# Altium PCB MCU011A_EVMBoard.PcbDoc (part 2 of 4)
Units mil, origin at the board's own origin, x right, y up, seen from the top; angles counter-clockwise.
Board outline 10115 x 9285 mil, 4 copper layers (Top Layer, GND, PWR, Bottom Layer), stack 61.2 mil thick; 438 components, 207 nets, 1196 pads, 248 vias.
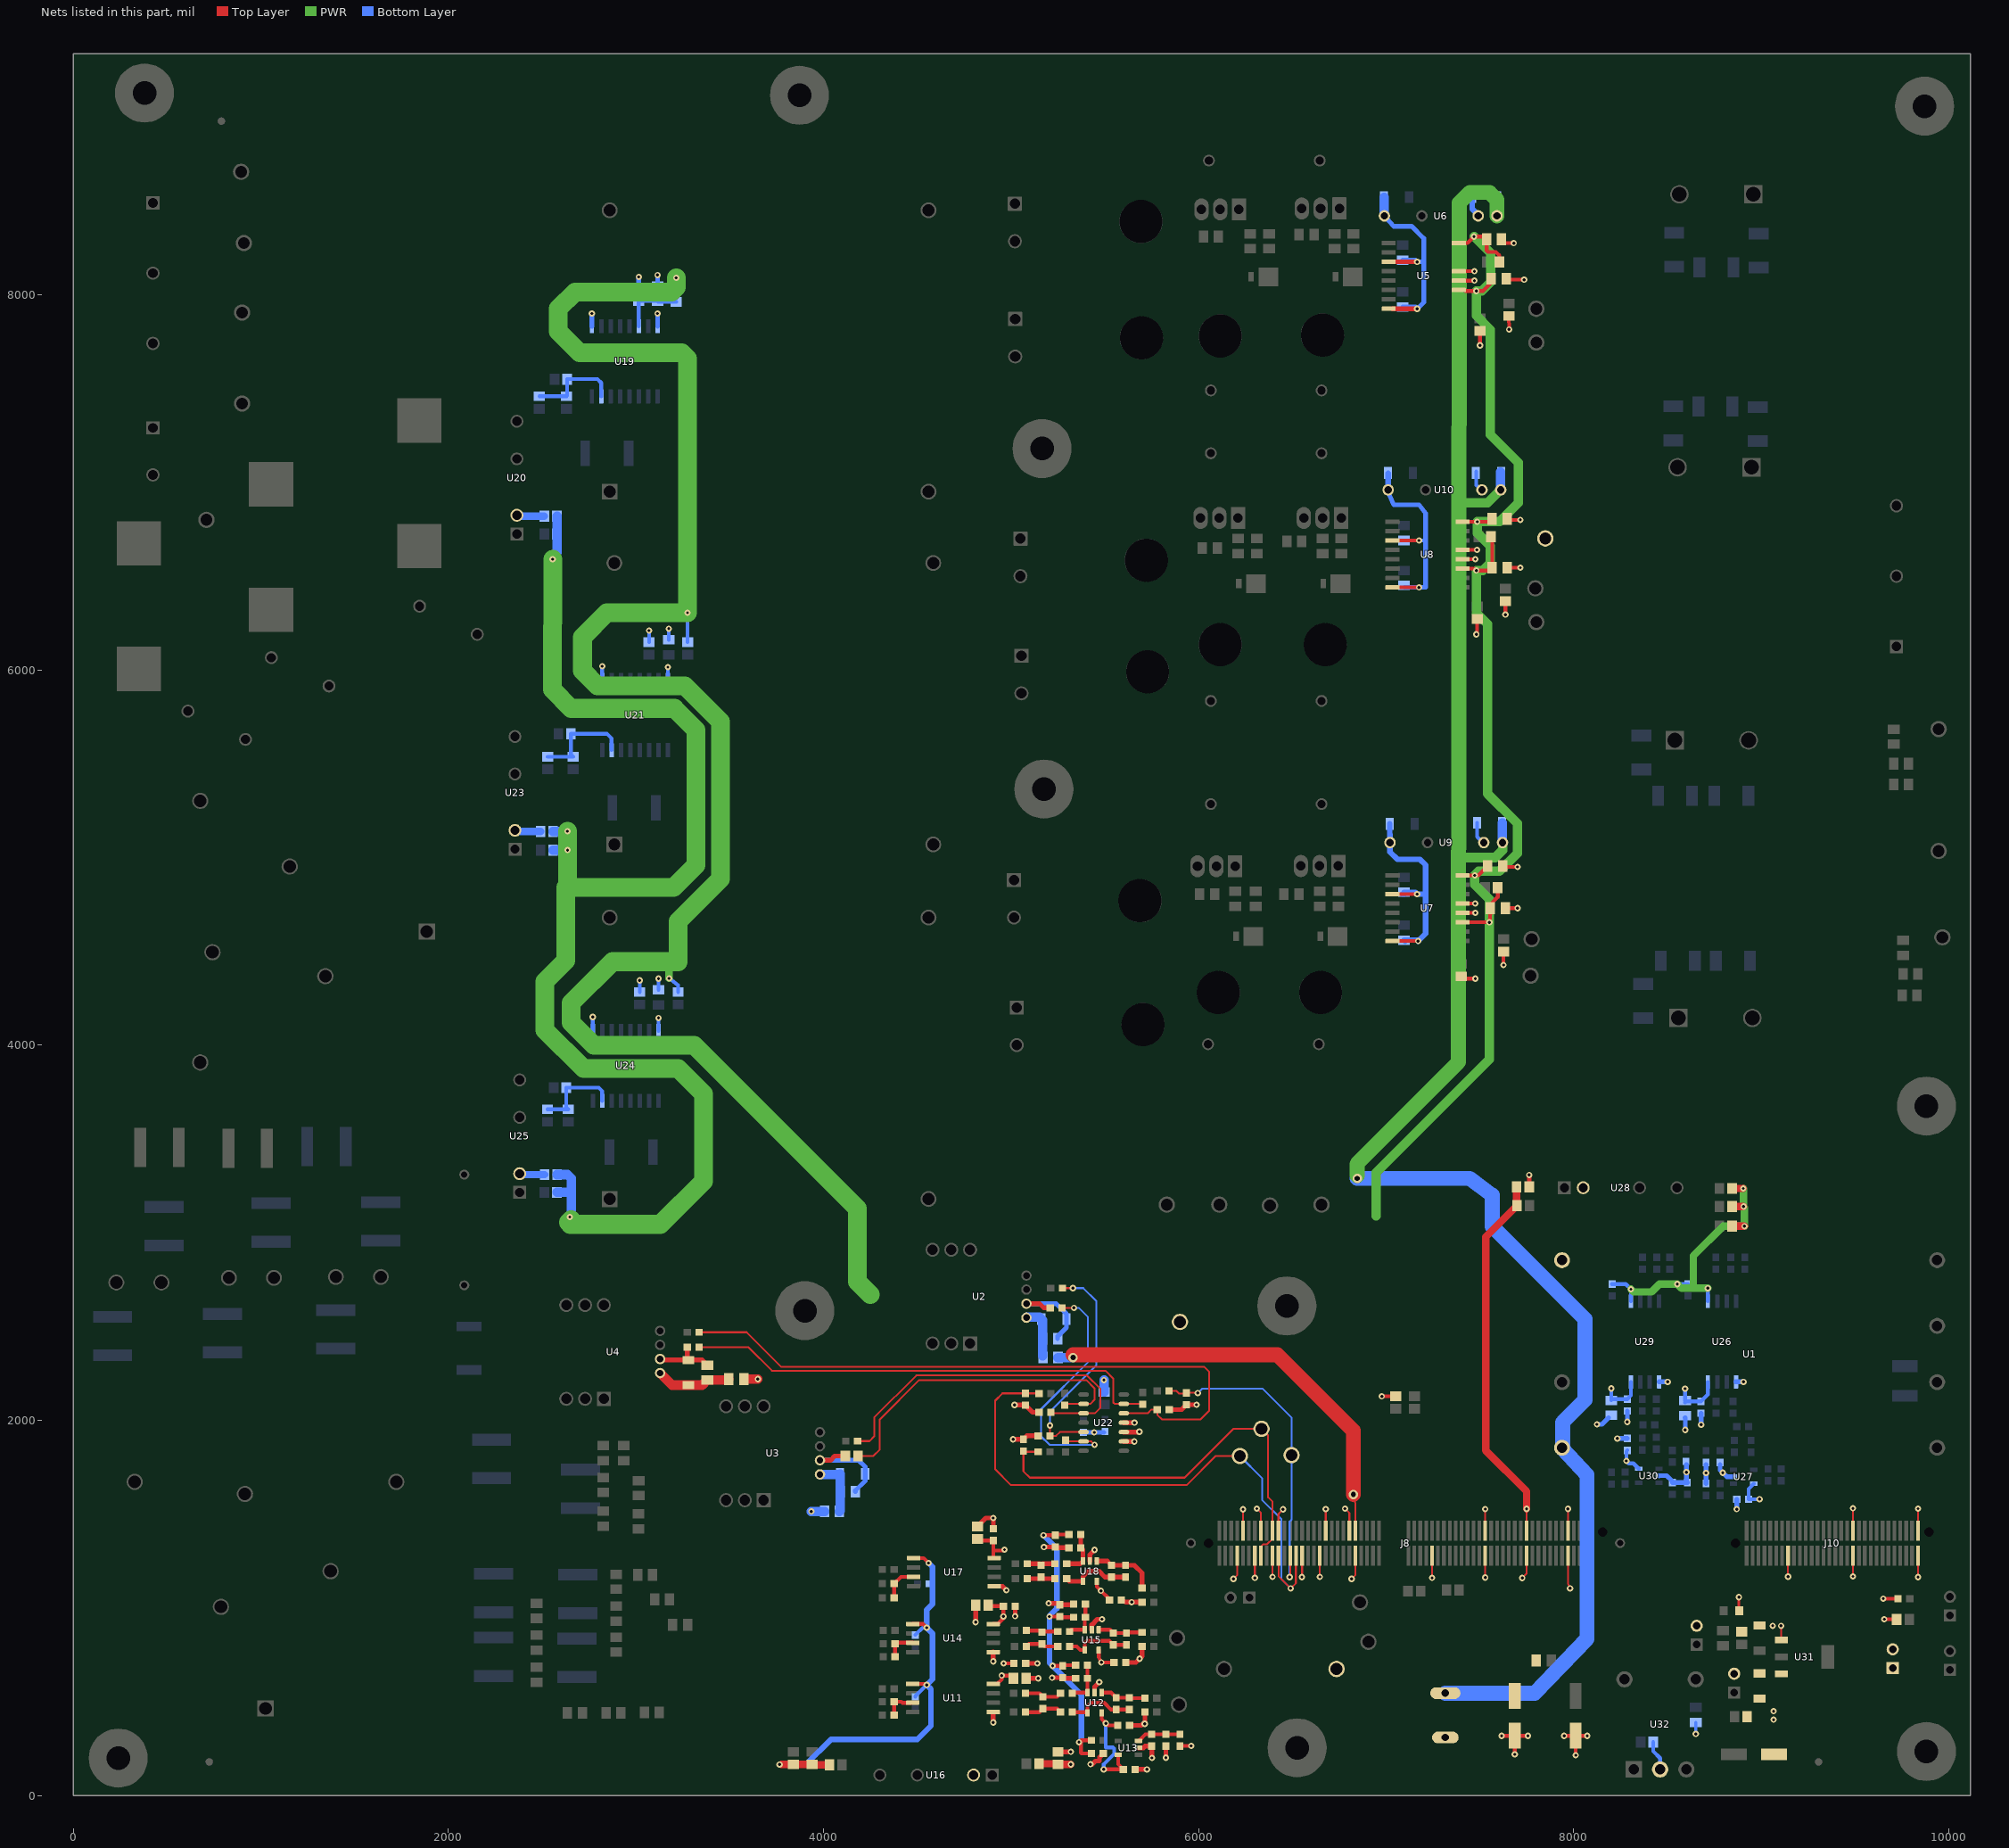
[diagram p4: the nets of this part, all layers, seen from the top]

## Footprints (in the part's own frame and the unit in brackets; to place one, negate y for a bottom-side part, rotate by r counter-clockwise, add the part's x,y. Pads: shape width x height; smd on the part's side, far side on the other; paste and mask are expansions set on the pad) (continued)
Phoenix_1714984 [mm] "Phoenix Contact"
  rect 1.8x1.8 hole 1.3 paste+0: 1(-9.52,1.65)
  round 1.8 hole 1.3 paste+0: 2(0,1.65) 3(9.52,1.65)
  silkscreen extent -14.85,-6.81 14.28,6.25, body extent -14.85,-6.25 14.28,6.25, height 21.51
POWERMITE [mil] "On Semi recommended land pattern, 457-04.pdf Rev 04E dated 2008-11-26"
  rect 105x100 smd: 1(-46,0)
  rect 30x50 smd: 2(46,0)
  silkscreen extent -124,-63 61,63, body extent -94,-40 59,40, height 45
PWR050 [mil] "TI PCBA"
  round 85 hole 55: 1(-1000,500) 2(-1000,-500) 3(-1000,150) 4(-1000,-150) 5(1000,500) 6(1000,150) 7(1000,-500)
  silkscreen extent -1100,-600 1100,600, body extent -1100,-600 1100,600, height 356
RP-1205S [mm] "Recom Power"
  round 1.55 hole 1: 1(-7.62,2.54) 2(-5.08,2.54) 5(2.54,2.54) 7(7.62,2.54)
  silkscreen extent -9.62,-3.24 10.03,3.81, body extent -9.62,-3.24 10.03,3.81, height 10.21
Samtec_HTSW-102-07-G-S [mm] "Samtec 100mil, 1x2, 230 mil above insulator"
  rrect6% 1.65x1.65 hole 1.016: 1(-1.27,0)
  round 1.65 hole 1.016: 2(1.27,0)
  silkscreen extent -3.3,-1.27 2.54,1.27, body extent -2.54,-1.27 2.54,1.27, height 8.38
SM_RADIAL_6.3BMM [mm] "Nichicon 6.3x7.7"
  rect 3.5x1.6 smd: 1(-2.7,0) 2(2.7,0)
  silkscreen extent -3.4,-3.4 3.4,3.4, body extent -3.4,-3.4 3.4,3.4, height 8
TI_Stacked_Overlay_Small [mil]
  silkscreen extent -418,-98 418,98
TO-220-2_HORIZ_INV [mm] "TO-220, 2-Leads, Horizontal"
  rrect5% 1.9x1.9 hole 1.4: 1(-2.54,0)
  round 1.9 hole 1.4: 2(2.54,0)
  silkscreen extent -5,-20.25 5,-1.3, body extent -5,-20.25 5,0.35, height 4.5
TO-220AB_HORIZONTAL [mil] "For SolarMagic, with tab facing heatsink, away from PCB"
  rrect5% 76x118.11 hole 50: 1(100,0)
  rrect100% 76x118.11 hole 50: 2(0,0) 3(-100,0)
  silkscreen extent -210,79 210,800, body extent -210,-12 210,800, height 192
WL-SMCW_Green_0805 [mm] "SMD, 2-Leads, Body 2x1.25mm"
  rect 1.1x1.2 smd: 1(-1.05,0) 2(1.05,0)
  silkscreen extent -2.4,-1.1 1.5,1.1, body extent -1,-0.62 1,0.63, height 0.7

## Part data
C1: "CAP, CERM, 0.47 µF, 500 V, +/- 10%, X7R, 1812", Cap_Case=1812, Manufacturer="Knowles Capacitors", Supplier Part Number 1=1608-1155-1-ND, TempCo=X7R, Tolerance_%=10, Value1=Unknown, Value2=500V, ValueDisplayed=0.47µF
C2 C4 C6 C12 C13 C21 C22 C24 C25 C109 C111: "CAP, CERM, 10 µF, 25 V, +/- 10%, X7R, 1206_190", Cap_Case=1206, Manufacturer=Kemet, Supplier Part Number 1=399-7442-1-ND, TempCo=X7R, Tolerance_%=10, Value1=Unknown, Value2=25V, ValueDisplayed=10µF
C3 C5 C7 C8 C9 C11 C14 C15 C17 C18 C20 C23 C55 C63 C66 C67 C73 C77 C81 C93 C103 C105 C108 C110: "CAP, CERM, 0.1 µF, 25 V, +/- 10%, X7R, 0805", Cap_Case=0805, Manufacturer=Kemet, Supplier Part Number 1=399-1168-1-ND, TempCo=X7R, Tolerance_%=10, Value1="0.064 ohm", Value2=25V, ValueDisplayed=0.1µF
C10 C16 C19 C53 C54 C64 C65 C71 C72 C79 C80 C91 C92: "CAP, CERM, 1 µF, 50 V, +/- 10%, X7R, 0805", Cap_Case=0805, Manufacturer=MuRata, Supplier Part Number 1=490-4736-1-ND, TempCo=X7R, Tolerance_%=10, Value1=Unknown, Value2=50V, ValueDisplayed=1µF
C26 C31 C34 C35 C39 C44 C46 C47 C49 C57 C59 C60 C82 C87 C89 C90 C94 C99 C101 C102: "CAP, CERM, 180 pF, 50 V, +/- 5%, C0G/NP0, 0603", Cap_Case=0603, Manufacturer=Kemet, Supplier Part Number 1=399-1064-1-ND, TempCo=C0G/NP0, Tolerance_%=5, Value1=Unknown, Value2=50V, ValueDisplayed=180pF
C27 C29 C30 C32 C33 C36 C37 C38 C40 C42 C43 C45 C48 C50 C52 C56 C58 C61 C69 C74 C75 C78 C83 C85 C86 C88 C95 C97 C98 C100: "CAP, CERM, 0.1 µF, 16 V, +/- 5%, X7R, 0603", Cap_Case=0603, Manufacturer=AVX, Supplier Part Number 1=478-3726-1-ND, TempCo=X7R, Tolerance_%=5, Value1="0.039 ohm", Value2=16V, ValueDisplayed=0.1µF
C28 C41 C51 C84 C96: "CAP, CERM, 4.7 µF, 50 V, +/- 10%, X5R, 0805", Cap_Case=0805, Manufacturer=TDK, Supplier Part Number 1=445-5980-1-ND, TempCo=X5R, Tolerance_%=10, Value1=Unknown, Value2=50V, ValueDisplayed=4.7µF
C62 C68 C76: "CAP, CERM, 2.2 µF, 16 V, +/- 10%, X5R, 0805", Cap_Case=0805, Manufacturer=AVX, Supplier Part Number 1=478-2580-1-ND, TempCo=X5R, Tolerance_%=10, Value1="0.009 ohm", Value2=16V, ValueDisplayed=2.2µF
C70: "CAP, CERM, 1 µF, 25 V, +/- 10%, X7R, 0603", Cap_Case=0603, Manufacturer=Kemet, Supplier Part Number 1=399-7376-1-ND, TempCo=X7R, Tolerance_%=10, Value1=Unknown, Value2=25V, ValueDisplayed=1µF
C104 C106 C107: library part EEHZA1E101XP, "CAP, Polymer Hybrid, 100 µF, 25 V, +/- 20%, 30 ohm, 6.3x7.7 SMD", Manufacturer=Panasonic, Supplier Part Number 1=P15436CT-ND, Tolerance_%=20, Value1="30 ohm", Value2=25V, ValueDisplayed=100µF
"CAUTION High Voltage" "CAUTION! High Voltage" "CAUTION! High Voltage Input" "CAUTION! High Voltage Output" "CAUTION! High Voltage!" "CAUTION! High Voltage!!" "CAUTION!! High Voltage" "CAUTION!! High Voltage!!!" "CAUTION!!! High Voltage!!!": library part IEC_HighVoltage, "IEC 61010-1 High Voltage Warning"
"CAUTION! HOT SURFACE!" "CAUTION! HOT SURFACE!!": library part IEC_HotSurface, "IEC 61010-1 Hot Surface Warning"
"CAUTION! Read User Guide Before Operating": library part IEC_Caution, "IEC 61010-1 Caution Warning"
Cbus1 Cbus4 Cbus5 Cbus6 Cbus7 Cbus10: "CAP, Film, 0.1 µF, 630 V, +/- 5%, TH", Cap_Case="Radial 18x7.7x13.6", Manufacturer=Panasonic, Supplier Part Number 1=P12158-ND, Tolerance_%=5, Value1=Unknown, Value2=630V, ValueDisplayed=0.1µF
Cbus2 Cbus3 Cbus8 Cbus9: "CAP, AL, 220 µF, 450 V, +/- 20%, 0.73 ohm, TH", Cap_Case=35x30mm, Manufacturer=TDK, Supplier Part Number 1=495-4262-ND, Tolerance_%=20, Value1="0.73 ohm", Value2=450V, ValueDisplayed=220µF
Cm1: "CAP, Film, 0.1 µF, 275 V, +/- 20%, TH", Cap_Case="Radial 17.5x5.5x12.5", Manufacturer=Panasonic, Supplier Part Number 1=P10730-ND, Tolerance_%=20, Value1=Unknown, Value2=275V, ValueDisplayed=0.1µF
Cvn1 Cvn2 Cvn3 Cvn4 Cvn5 Cvn6 Cx1 Cx2 Cx3 Cx4 Cx5 Cx6 Cy1 Cy2 Cy3: "CAP, CERM, 2200 pF, 250 V, +/- 10%, X7R, 2220", Cap_Case=2220, Manufacturer=MuRata, Supplier Part Number 1=490-3480-1-ND, TempCo=X7R, Tolerance_%=10, Value1=Unknown, Value2=250V, ValueDisplayed=2200pF
D1 D2 D3 D4 D5 D6: "Diode, Schottky, 1200 V, 8 A, TH", Manufacturer=Cree, Supplier Part Number 1=C4D08120A-ND, Value1=8A, Value2=1.8V
D7 D8 D9 D10 D11 D12: "Diode, Schottky, 30 V, 1 A, POWERMITE", Manufacturer="ON Semiconductor", Supplier Part Number 1=MBRM130LT1GOSCT-ND, Value1=1A, Value2=0.38V
D13: "LED, Bright Green, SMD", Color="Bright Green", Manufacturer="Wurth Elektronik", Power_TotalModule=0.072, Supplier Part Number 1=732-4986-1-ND, Value1=0.072W, Value2=2V
FID1 FID2 FID3 FID4 FID5 FID6: "Fiducial mark.  There is nothing to buy or mount.", Manufacturer=N/A
H1 H2 H3 H4 H5 H6 H7 H8 H9 H10 H11: "Machine Screw, Round, #4-40 x 1/4, Nylon, Philips panhead", DigiKeyPartNumber=H542-ND, Manufacturer="B&F Fastener Supply"
J1 J2: "Terminal Block, 3x1, 9.52MM, TH", Manufacturer="Phoenix Contact", Supplier Part Number 1=277-1272-ND
J3: "Terminal Block, 2x1, 6.35mm, Green, TH", Color=Green, Manufacturer="Phoenix Contact", Supplier Part Number 1=277-1269-ND
J4: "Power Jack, 2mm, R/A, TH", Color=Black, Manufacturer="CUI Inc.", Supplier Part Number 1=CP-037AH-ND
J5 J6 J7 J9 J11 J12: "Header, 100mil, 2x1, Gold, TH", Manufacturer=Samtec, Supplier Part Number 1=SAM8736-ND
J8: library part controlCARD-120HSEC, "C2000 controlCARD-120HSEC connector, SMT", Manufacturer=Samtec
J10: library part controlCARD-180HSEC-60pinAddon, "C2000 controlCARD-180HSEC (60-pin addon) connector, SMT", Manufacturer=Samtec
L1 L3 L6 L7 L8 L9 L10 L11 L12 L13 L14 L15 L16 L17 L18 L19 L20 L21: "Ferrite Bead, 30 ohm @ 100 MHz, 6 A, 0805", Manufacturer=TDK, Supplier Part Number 1=445-1566-1-ND, Value1="0.01 ohm", Value2=6A
L2 L4 L5: "Inductor, 0.2 ohm, TH", Manufacturer="Vitec Corporation", Value1="0.2 ohm", Value2=A
Lcm1 Lcm2: "Inductor, 1.6 mH, 0.008 ohm, TH", Manufacturer="Vitec Corporation", Value1="0.008 ohm", Value2=A, ValueDisplayed=1.6mH
Ldm1 Ldm2 Ldm3: "Inductor, Toroid, 20.5 A, 0.0055 ohm, TH", Manufacturer="Pulse Engineering", Supplier Part Number 1=553-1503-ND, Value1="0.0055 ohm", Value2=20.5A
Logo1: library part TI_Logo, "Texas Instrument Corporate Signature"
Logo2: library part Pb-Free
Logo3: library part FCC_disclaimer, "FCC_disclaimer"
Q1 Q2 Q3 Q4 Q5 Q6: library part IPP65R190C7, "MOSFET, N-CH, 700 V, 13 A, TO-220AB", Alternate Manufacturer=None, Manufacturer="Infineon Technologies", Supplier Part Number 1=IPP65R190C7FKSA1-ND, Value1="? ohm", Value2="23 nC"
R1 R2 R9 R17 R18: "RES, 499 k, 1%, 0.1 W, AEC-Q200 Grade 0, 0603", Manufacturer=Panasonic, Power_W=0.1, Supplier Part Number 1=P499KHCT-ND, TempCo="100 ppm/C", Tolerance_%=1, Value1=1%, Value2=0.1W, Value_Code=499k
R3 R4 R5 R6 R7 R8 R11 R12 R13 R14 R15 R16: "RES, 510 k, 5%, 0.75 W, AEC-Q200 Grade 0, 2010", Manufacturer=Vishay-Dale, Power_W=0.75, Supplier Part Number 1=541-510KWCT-ND, TempCo="200 ppm/C", Tolerance_%=5, Value1=5%, Value2=0.75W, Value_Code=510k
R10: "RES, 499 k, 1%, 0.125 W, 0805", Manufacturer=Vishay-Dale, Power_W=0.125, Supplier Part Number 1=541-499KCCT-ND, TempCo="100 ppm/C", Tolerance_%=1, Value1=1%, Value2=0.125W, Value_Code=499k
R19 R24 R25 R28 R33 R34 R36 R42 R43 R118 R121: "RES, 0, 5%, 0.125 W, 0805", Manufacturer=Vishay-Dale, Power_W=0.125, Supplier Part Number 1=541-0.0ACT-ND, TempCo="200 ppm/C", Tolerance_%=5, Value1=5%, Value2=0.125W, Value_Code=0000, ValueDisplayed=0
R20 R26 R29 R35 R38 R44: "RES, 10, 5%, 0.125 W, 0805", Manufacturer=Vishay-Dale, Power_W=0.125, Supplier Part Number 1=541-10ACT-ND, TempCo="200 ppm/C", Tolerance_%=5, Value1=5%, Value2=0.125W, Value_Code=10R0, ValueDisplayed=10
R21 R22 R23 R27 R30 R31 R32 R37 R39 R40 R41 R45 R120: "RES, 10.0 k, 0.1%, 0.125 W, 0805", Manufacturer="Yageo America", Power_W=0.125, Supplier Part Number 1=603-RT0805BRD0710KL, TempCo="25 ppm/C", Tolerance_%=0.1, Value1=0.1%, Value2=0.125W, Value_Code=10k0, ValueDisplayed=10.0k
R46 R47 R49 R61 R62 R64 R73 R74 R76 R94 R95 R97 R106 R107: "RES, 1.0 M, 5%, 0.125 W, 0805", Manufacturer=Vishay-Dale, Power_W=0.125, Supplier Part Number 1=541-1.0MACT-ND, TempCo="200 ppm/C", Tolerance_%=5, Value1=5%, Value2=0.125W, Value_Code=1M00, ValueDisplayed=1.0M
R48 R57 R63 R72 R75 R84 R96 R105 R108 R117: "RES, 7.50 k, 1%, 0.1 W, 0603", Manufacturer=Panasonic, Power_W=0.1, Supplier Part Number 1=P7.50KHCT-ND, TempCo="100 ppm/C", Tolerance_%=1, Value1=1%, Value2=0.1W, Value_Code=7k50, ValueDisplayed=7.50k
R50 R51 R54 R55 R65 R66 R69 R70 R77 R78 R81 R82 R98 R99 R102 R103 R110 R111 R114 R115: "RES, 4.70 k, 1%, 0.1 W, 0603", Manufacturer="Yageo America", Power_W=0.1, Supplier Part Number 1=311-4.70KHRCT-ND, TempCo="200 ppm/C", Tolerance_%=1, Value1=1%, Value2=0.1W, Value_Code=4k70, ValueDisplayed=4.70k
R52 R56 R67 R71 R79 R83: "RES, 2.00 k, 1%, 0.1 W, 0603", Manufacturer=Vishay-Dale, Power_W=0.1, Supplier Part Number 1=541-2.00KHCT-ND, TempCo="100 ppm/C", Tolerance_%=1, Value1=1%, Value2=0.1W, Value_Code=2k00, ValueDisplayed=2.00k
R53 R68 R80 R87 R88 R92 R101 R113 R122: "RES, 68.1, 1%, 0.1 W, 0603", Manufacturer=Vishay-Dale, Power_W=0.1, Supplier Part Number 1=541-68.1HCT-ND, TempCo="100 ppm/C", Tolerance_%=1, Value1=1%, Value2=0.1W, Value_Code=68R1, ValueDisplayed=68.1
R58 R60: "RES, 10.0 k, 1%, 0.1 W, 0603", Manufacturer=Vishay-Dale, Power_W=0.1, Supplier Part Number 1=541-10.0KHCT-ND, TempCo="100 ppm/C", Tolerance_%=1, Value1=1%, Value2=0.1W, Value_Code=10k0, ValueDisplayed=10.0k
R59: "RES, 10.0, 1%, 0.1 W, 0603", Manufacturer=Vishay-Dale, Power_W=0.1, Supplier Part Number 1=541-10.0HCT-ND, TempCo="100 ppm/C", Tolerance_%=1, Value1=1%, Value2=0.1W, Value_Code=10R0, ValueDisplayed=10.0
R85 R86 R89 R90 R91 R93: "RES, 330 k, 1%, 0.1 W, AEC-Q200 Grade 0, 0603", Manufacturer=Panasonic, Power_W=0.1, Supplier Part Number 1=P330KHCT-ND, TempCo="100 ppm/C", Tolerance_%=1, Value1=1%, Value2=0.1W, Value_Code=330k
R100 R104 R112 R116: "RES, 2.74 k, 1%, 0.1 W, 0603", Manufacturer=Vishay-Dale, Power_W=0.1, Supplier Part Number 1=541-2.74KHCT-ND, TempCo="100 ppm/C", Tolerance_%=1, Value1=1%, Value2=0.1W, Value_Code=2k74, ValueDisplayed=2.74k
R109: "RES, 1.00 M, 0.1%, 0.125 W, 0805", Manufacturer="Yageo America", Power_W=0.125, Supplier Part Number 1=603-RT0805BRD071ML, TempCo="25 ppm/C", Tolerance_%=0.1, Value1=0.1%, Value2=0.125W, Value_Code=1M00, ValueDisplayed=1.00M
R119: "RES, 3.3 k, 5%, 0.125 W, 0805", Manufacturer=Vishay-Dale, Power_W=0.125, Supplier Part Number 1=541-3.3KACT-ND, TempCo="200 ppm/C", Tolerance_%=5, Value1=5%, Value2=0.125W, Value_Code=3k30, ValueDisplayed=3.3k
R123: "RES, 470, 1%, 0.125 W, 0805", Manufacturer=Vishay-Dale, Power_W=0.125, Supplier Part Number 1=541-470CCT-ND, TempCo="100 ppm/C", Tolerance_%=1, Value1=1%, Value2=0.125W, Value_Code=470R, ValueDisplayed=470
R124: "RES, 348, 1%, 0.125 W, 0805", Manufacturer=Vishay-Dale, Power_W=0.125, Supplier Part Number 1=541-348CCT-ND, TempCo="100 ppm/C", Tolerance_%=1, Value1=1%, Value2=0.125W, Value_Code=348R, ValueDisplayed=348
RN1 RSH1 RSH2 RSH3: "RES, 0.02, 1%, 3 W, 2512", Manufacturer=Bourns, Power_W=3, Supplier Part Number 1=CRA2512-FZ-R020ELFCT-ND, TempCo="75 ppm/C", Tolerance_%=1, Value1=1%, Value2=3W, Value_Code=R020, ValueDisplayed=0.02
RT1 RT2 RT3: "ICL, 10OHM, 20%, 15A, TH", Manufacturer=Ametherm, Supplier Part Number 1=570-1058-ND
Rvn1 Rvn2 Rvn3 Rvn4 Rvn5 Rvn6 Rvn7 Rvn8 Rvn9: "RES, 2.00 M, 1%, 0.125 W, AEC-Q200 Grade 0, 0805", Manufacturer=Panasonic, Power_W=0.125, Supplier Part Number 1=P2.00MCCT-ND, TempCo="100 ppm/C", Tolerance_%=1, Value1=1%, Value2=0.125W, Value_Code=2M00, ValueDisplayed=2.00M
SH-J1 SH-J2: "Shunt, 2mm, Gold plated, Black", Manufacturer=Samtec, Supplier Part Number 1=2SN-BK-G-ND
TP1 TP2 TP3 TP4 TP5 TP6: "Test Point, Multipurpose, Yellow, TH", Color=Yellow, Manufacturer=Keystone, Supplier Part Number 1=36-5014-ND
TP_BUSM1 TP_N1: "Test Point, Multipurpose, White, TH", Color=White, Manufacturer=Keystone, Supplier Part Number 1=36-5012-ND
TP_BUSN1 TP_VL1: "Test Point, Multipurpose, Black, TH", Color=Black, Manufacturer=Keystone, Supplier Part Number 1=36-5011-ND
TP_BUSP1 TP_VL2: "Test Point, Multipurpose, Red, TH", Color=Red, Manufacturer=Keystone, Supplier Part Number 1=36-5010-ND
TP_E1: "Test Point, Multipurpose, Green, TH", Color=Green, Manufacturer=Keystone, Supplier Part Number 1=36-5126-ND
TP_GND1 TP_GND2 TP_GND3: "Test Point, Multipurpose, Grey, TH", Color=Grey, Manufacturer=Keystone, Supplier Part Number 1=36-5128-ND
TP_IL1 TP_IL2 TP_IL3 TP_VBUSMN_Fdbk1 TP_VBUSPM_Fdbk1 TP_VL1_Fdbk TP_VL2_Fdbk TP_VL3_Fdbk: "Test Point, Multipurpose, Orange, TH", Color=Orange, Manufacturer=Keystone, Supplier Part Number 1=36-5013-ND
TP_SD_CLKI1 TP_SD_DATA_1 TP_SD_DATA_2 TP_SD_DATA_3: "Test Point, Multipurpose, Purple, TH", Color=Purple, Manufacturer=Keystone, Supplier Part Number 1=36-5129-ND
TP_VL3: "Test Point, Multipurpose, Blue, TH", Color=Blue, Manufacturer=Keystone, Supplier Part Number 1=36-5127-ND
U1: "PCBA, UCC28600EVM-400V-12V", Manufacturer="Texas Instruments"
U2 U3 U4: "Current Transducer, AC/DC, 6A, TH", Manufacturer=LEM, Supplier Part Number 1=398-1021-5-ND
U5 U7 U8: "4A/6A, 5.7 kVrms Isolated Dual Channel Gate Driver, DW0016B (SOIC-16)", Alternate Manufacturer="Texas Instruments", Alternate PartNumber=UCC21520DW
U6 U9 U10: "1 Watt Single Output, TH", Manufacturer="Recom Power", Supplier Part Number 1=945-1254-ND
U11 U14 U17 U26 U29: "Precision +/-250-mV Input, 3-us Delay, Reinforced Isolated Amplifier, DWV0008A (SOIC-8)", Alternate Manufacturer="Texas Instruments", Alternate PartNumber=AMC1301DWV
U12 U13 U15 U18 U27 U30: "Precision, 20 MHz, 0.9 pA Ib, RRIO, CMOS Operational Amplifier, 1.8 to 5.5 V, -40 to 125 degC, 5-pin SOT23 (DBV0005A), Green (RoHS & no Sb/Br)", Alternate Manufacturer="Texas Instruments", Alternate PartNumber=Equivalent, Supplier Part Number 1=296-29480-2-ND, Total Supply Voltage(Max)(+5V is 5, +/-5V is 10)=5.5, Total Supply Voltage(Min)(+5V is 5, +/-5V is 10)=1.8
U16 U20 U23 U25 U28: "Miniature, 1 W, 3 kVDC Isolated DC-DC Converter, -40 to 85 degC, 4-pin Module (EDJ4), Pb-Free (RoHS)", Alternate Manufacturer="Texas Instruments", Alternate PartNumber=Equivalent, Supplier Part Number 1=296-20638-ND
U19 U21 U24: "Reinforced Isolated Modulator with ±250mV Input and CMOS Interface, DW0016B (SOIC-16)", Alternate Manufacturer="Texas Instruments", Alternate PartNumber=AMC1305M25DW
U22: "High-Speed, Single-Supply, Rail-to-Rail Operational Amplifier MicroAmplifier(TM) Series, 2.7 to 5.5 V, -55 to 150 degC, 14-pin SOIC (D0014A), Green (RoHS & no Sb/Br)", Alternate Manufacturer="Texas Instruments", Alternate PartNumber=Equivalent, Supplier Part Number 1=OPA4350UA-ND, Total Supply Voltage(Max)(+5V is 5, +/-5V is 10)=5.5, Total Supply Voltage(Min)(+5V is 5, +/-5V is 10)=2.7
U31: "FIXED LOW-DROPOUT VOLTAGE REGULATOR, DCY0004A", Alternate Manufacturer="Texas Instruments"
U32: "2.25 A, 4.5 to 18 V Input Wide Adjust Miniature Power Module, -40 to 85 degC, 5-pin Module (EUF5), Pb-Free (RoHS)", Alternate Manufacturer="Texas Instruments", Alternate PartNumber=Equivalent, Supplier Part Number 1=296-20432-ND
XF1 XF2 XF3: "FuseHolder for 5x20mm Fuses, SMT", Manufacturer=Littelfuse, Supplier Part Number 1=F4546-ND
ZZ1 ZZ2 ZZ3 ZZ4 ZZ5 ZZ6: library part AssemblyNote, Alternate Manufacturer=-

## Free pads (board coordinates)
  round 230 hole 230: 0(5687,4770) 0(5692,8390) 0(5695,7770) 0(5703,4110) 0(5721,6585) 0(5728,5990) 0(6105,4281) 0(6115,6135) 0(6115,7780) 0(6650,4281) 0(6660,7785) 0(6675,6135)

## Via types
v1: diameter 34, hole 16, Top Layer to Bottom Layer, 243 vias
v2: diameter 50, hole 28, Top Layer to Bottom Layer, 5 vias

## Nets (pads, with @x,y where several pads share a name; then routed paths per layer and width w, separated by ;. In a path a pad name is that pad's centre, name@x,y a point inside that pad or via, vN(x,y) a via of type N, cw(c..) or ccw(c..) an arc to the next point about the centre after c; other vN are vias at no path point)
1.65V: C36.2 C37.1 C48.2 C61.1 R57.1 R59.2 R72.1 R84.1 | length 1800
  Top Layer w20: v1(5172.8,1387.8) C61.1@5235,1387.8 5238.5,1391.3 R84.1@5308.5,1391.3 ; v1(5204.5,954.5) C48.2@5260,954.5 5263.5,951 R72.1@5333.5,951 ; v1(5221.5,691.5) C37.1@5275,691.5 5278.5,695 R57.1@5343.5,695 ; v1@5360,283 v1(5362,285) ; v1@5372,283 5372,228 5375,225 C36.2@5428.5,225 ; v1@5372,285 5372,295 R59.2@5428.5,295
  Bottom Layer w20: v1(5204.5,954.5) v1@5204.5,957.68 ; v1(5362,285) 5372,295 v1@5375,295
  Bottom Layer w30: v1(5172.8,1387.8) 5244.5,1316.09 5244.5,997.67 v1@5204.5,957.68 ; v1(5204.5,954.5) 5204.5,708.49 v1(5221.5,691.5) 5375,537.99 v1@5375,295
3.3V: C9.1 C10.1 C15.1 C16.1 C18.1 C19.1 C28.2 C29.2 C30.1 C32.1 C41.2 C42.1 C43.2 C51.2 C52.2 C56.1 C84.2 C85.1 C86.1 C96.2 C97.2 C98.1 J12.2 L9.2 L12.2 L13.2 L16.2 R24.2 R33.2 R42.2 R58.2 R119.2 U5.3 U5.8 U7.3 U7.8 U8.3 U8.8 U11.8 U12.5 U13.5 U14.8 U15.5 U17.8 U18.5 U26.8 U27.5 U29.8 U30.5 | length 19796.7
  Top Layer w10: R42.2@7558.46,6710 R42.2@7565,6716.54
  Top Layer w20: C51.2@4820,1367.83 4828.03,1359.8 C52.2@4905,1359.8 4905,1306 ; C41.2@4878.46,1015 4883.46,1010 C42.1@4958.5,1010 v1(4958.5,955) 4958.5,943.5 4930,915 U14.8@4904.57,915 ; U11.8@4904.57,595 4925,595 4950,620 v1(4950,640) 4997.83,640 C28.2@5012.83,625 ; U17.8@4909.57,1266.3 4905,1270.87 4905,1306 ; v1(4960,705) C29.2@5014.8,705 ; v1(4965,1311) 4960,1306 4905,1306 ; U18.5@5457.4,1142.17 5457.4,1113.6 v1(5479,1092) 5519.7,1051.3 C56.1@5528.5,1051.3 ; U15.5@5467.4,775.87 5467.4,737.6 v1(5481,710) C43.2@5548.5,710 ; U12.5@5482.4,440.87 5482.4,407.6 v1(5505,385) 5515,375 C30.1@5568.5,375 ; v1(5494,140) C32.1@5598.5,140 5570.87,167.64 U13.5@5570.87,217.6 ; R58.2@5900,263.5 5901.5,265 v1(5960,265) ; U5.8@7387.01,8275 7433,8275 v1(7468,8310) C9.1@7540,8310 ; U7.3@7407.01,4655 v1(7550,4655) ; U7.8@7407.01,4905 v1(7472.01,4905) 7490,4905 C15.1@7540,4955 ; U8.3@7407.01,6540 7470,6540 v1(7480,6530) 7550,6530 C19.1@7565,6545 7565,6703.46 R42.2@7558.46,6710 ; U8.8@7407.01,6790 v1(7485,6790) C18.1@7557.99,6790 ; U5.3@7417.01,8025 7422.01,8020 v1(7480,8020) 7515,8020 7560,8065 C10.1@7560,8085 ; C9.1@7535,8275 7535,8235 7541.5,8228.5 7584.6,8228.5 7603.46,8209.64 R24.2@7603.46,8175 ; v1@7552.01,4655 C16.1@7555,4730 7555,4750 7595,4790 7595,4838.46 R33.2@7593.46,4840 ; v1(9655,940) R119.2@9721.54,940
  PWR w40: v1(3177,4356) 3177,4446
  PWR w50: 6945,3090 6945,3320 7550,3925 v1(7550,4655) 7550,4778.15 7472.01,4856.14 v1(7472.01,4905) 7493.46,4926.46 7602.92,4926.46 7698.74,5022.28 7698.74,5181.26 7540,5340 7540,6244.07 7480,6304.07 v1(7480,6530) 7515,6530 7555,6570 7555,6660.32 7485,6730.32 v1(7485,6790) 7604.76,6790 7705,6890.24 7705,7105 7555,7255 7555,7813.52 7480,7888.52 v1(7480,8020) 7510,8020 7556.69,8066.69 7556.69,8221.31 v1(7468,8310)
  PWR w100: v1(3215,8090) 3215,8040.59 3189.41,8015 2675,8015 2585,7925 2585,7805 2700,7690 3245,7690 3275,7660 v1(3275,6305) 2845,6305 2715,6175 2715,5995 2795,5915 3260,5915 3450,5725 3450,4885 3225,4660 3225,4445 2875,4445 2655,4225 2655,4120 2775,4000 3310,4000 4180,3130 4180,2740 4250,2670
  Bottom Layer w20: v1(3177,4356) 3225,4320 L16.2@3225,4283.46 ; L9.2@3215,8028.46 v1(3215,8090) ; L12.2@3275,6148.46 v1(3275,6305) ; v1(5494,140) 5494,168 5549,223 5549,251 5543,257 5505,257 v1(5505,385) ; v1(8200,2170) C96.2@8200,2106.95 8206.5,2113.45 C97.2@8285,2113.45 8304.41,2132.85 U29.8@8304.41,2205.43 ; C98.1@8285,1840.45 8280,1835.45 v1(8280,1784) 8292.81,1771.19 8301.98,1771.19 8302.22,1770.95 8317.32,1770.95 U30.5@8345.86,1742.41 ; C84.2@8593,2106 v1(8593,2169.32) ; C84.2@8593.09,2094.77 8599.58,2101.26 C85.1@8678.09,2101.26 8714.41,2137.58 U26.8@8714.41,2205.43 ; U27.5@8959.13,1662.6 8931.49,1634.96 C86.1@8931.49,1580.01 v1(8990.01,1580.01)
  Bottom Layer w50: v1(5495,2215) 5495,2152.16 L13.2@5495.96,2151.2
5V: C53.1 C64.1 C71.1 C79.1 C91.1 C111.1 J8.48 J8.84 J8.98 J8.112 J10.158 J10.180 J11.2 L1.2 L3.2 L6.2 L7.1 L10.1 L14.1 L17.1 L19.1 U31.3 | length 12211
  Top Layer w10: v2(6825,1605) 6834.84,1555.16 J8.48@6834.84,1412.8 ; J8.84@7527.76,1412.8 v1(7527.76,1527.24) ; J8.98@7748.23,1412.8 v1(7748.23,1528.23) ; J8.112@7968.7,1412.8 v1(7968.7,1528.7) ; J10.158@9488.39,1412.8 v1(9488.39,1531.61) ; J10.180@9834.84,1412.8 v1(9834.84,1529.84)
  Top Layer w40: L7.1@5148.46,170 5246.54,170 C53.1@5250,166.54 v1(5318.46,166.54) ; L19.1@7695,3145.91 C91.1@7695,3244.37 ; L19.1@7696.54,3144.37 7530,2977.83 7530,1840 7748.23,1621.77 v1(7748.23,1528.23)
  Top Layer w50: L6.2@3575,2220 v1(3650,2220)
  Top Layer w80: v2@5330,2350 6420,2350 6815,1955 ; v2(6825,1605) 6825,1945
  PWR w100: v1(2556,6590) 2555,5895 2655,5795 3205,5795 3320,5680 3320,4960 3200,4840 2625,4840 ; v1(2635,5140) 2635,5040.31 v1(2635.32,5040) 2635.32,4850.31 2625,4840 ; v1@2655,3070 2640,3055 2650,3045 3130,3045 3360,3275 3360,3740 3225,3875 2720,3875 2515,4080 2515,4340 2625,4450 2625,4840
  Bottom Layer w50: v1(2556,6590) 2556,6605.51 2578.47,6627.97 L10.1@2578.46,6725 C64.1@2578.46,6820 ; L14.1@2558.46,5040 v1(2635.32,5040) ; C71.1@2558.46,5140 v1(2635,5140) ; L17.1@2578.46,3215 2578.78,3215.31 2655,3215.31 ; C79.1@2580,3310 2635,3310 2655,3290 2655,3215.31 ; v1(2647,3084) 2655,3092 2655,3215.31 ; v1(3935,1515) L3.2@4005,1515 ; L1.2@5250,2335 v2(5330,2335)
5V_1: C65.1 C66.1 L11.2 U19.7 | length 499.8
  Bottom Layer w20: C65.1@2485,7458.46 C66.1@2630,7458.46 2633.46,7461.93 L11.2@2633.46,7550 2795,7550 2815,7530 U19.7@2815,7457.99
5V_2: C72.1 C73.1 L15.2 U21.7 | length 552.1
  Bottom Layer w20: C72.1@2530,5536.93 C73.1@2665,5536.93 2653.46,5548.46 L15.2@2653.46,5660 2845,5660 2870,5635 U21.7@2870,5572.68
5V_3: C80.1 C81.1 L18.2 U24.7 | length 480.3
  Bottom Layer w20: C80.1@2528.52,3658.46 C81.1@2638.52,3658.46 2628.52,3668.46 L18.2@2628.52,3773.46 2801.54,3773.46 2820,3755 U24.7@2820,3702.99
5V_M: C83.1 C92.1 C93.1 C95.1 L20.2 U26.1 U29.1 | length 1649.3
  Top Layer w40: C92.1@8843.46,3035 v1(8910,3035) ; C93.1@8843.46,3140 v1(8905,3140) ; L20.2@8843.46,3236.48 v1(8903.52,3236.48)
  PWR w40: v1(8304.41,2699.41) 8318.82,2685 8415,2685 8456.5,2726.5 v1(8551.5,2726.5) 8573.58,2704.41 8637.24,2704.41 ; v1(8714.41,2704.41) 8637.24,2704.41 ; v1(8903.52,3236.48) 8905,3235 v1(8905,3140) 8910,3135 v1(8910,3035) 8795,3035 8637.24,2877.24 8637.24,2704.41
  Bottom Layer w20: C95.1@8203.7,2726.5 8277.32,2726.5 v1(8304.41,2699.41) U29.1@8304.41,2634.57 ; v1(8551.5,2726.5) C83.1@8608.7,2726.5 ; U26.1@8714.41,2634.57 v1(8714.41,2704.41)
5V_N2: C27.2 C40.1 C50.2 C54.1 C55.1 L8.2 U11.1 U14.1 U17.1 | length 2475.6
  Top Layer w20: U11.1@4475.43,595 4545,595 v1(4550,590) ; U14.1@4475.43,915 4530,915 v1(4550,895) ; U17.1@4480.43,1266.3 4533.7,1266.3 v1(4560,1240)
  Top Layer w40: v1@3776.54,166.54 C54.1@3840,166.54 C55.1@3940,166.54 3941.54,165 L8.2@4031.54,165
  Bottom Layer w20: C27.2@4490,526.5 4490,530 v1(4550,590) ; C40.1@4490,856.5 4528.5,895 v1(4550,895)
  Bottom Layer w30: v1@3776.54,166.54 3906.54,166.54 4040,300 4500,300 4573,373 4573,567 v1(4550,590) 4581,621 4581,864 v1(4550,895) 4550,990 4581,1021 4581,1219 v1(4560,1240)
  other v1: 3766,166
12V: C12.1 C21.1 C24.1 C104.1 J4.1 L21.2 U1.5 U6.1 U9.1 U10.1 | length 10898.5
  PWR w50: 7372.5,4982.5 7390,5000 7580,5000 7620,5040 U9.1@7620,5080 ; 7380,6875 7395,6890 7540,6890 U10.1@7610,6960
  PWR w80: v2@6845,3305 6845,3365 ; 6850,3375 7385,3910 7390,8430 7390,8490 7445,8545 7551.93,8545 7590,8506.93 U6.1@7590,8420
  Bottom Layer w50: U6.1@7590,8420 7591.93,8421.93 C12.1@7591.93,8520 ; U10.1@7610,6960 C24.1@7610,7055 ; C21.1@7618.23,5185 7618.23,5081.77 U9.1@7620,5080
  Bottom Layer w80: v2(6845,3290) 7445,3290 7565,3200 7565,3035 8060,2540 8060,2110 7940,1990 7940,1850 8070,1710 8070,835 7791.22,546.22 J4.1@7315,546.22
12V_ISO_1: C8.1 C11.1 C13.1 U5.11 U5.16 U6.7 | length 1234
  Top Layer w25: U5.11@7012.99,8175 v1(7165,8175) ; U5.16@7032.99,7925 v1(7165,7925)
  Bottom Layer w25: U6.7@6990,8420 7040,8365 7135,8365 7200,8300 7200,8175 ; C8.1@7086.99,7934 7156,7934 v1(7165,7925) 7200,7960 7200,8175 ; C11.1@7086.99,8184 7156,8184 v1(7165,8175) 7200,8175
  Bottom Layer w50: C13.1@6988.07,8520 6988.07,8421.93 U6.7@6990,8420
12V_ISO_2: C17.1 C23.1 C25.1 U8.11 U8.16 U10.7 | length 1293.8
  Top Layer w20: U8.11@7030,6690 v1@7170,6690 ; U8.16@7032.99,6440 v1(7175,6440) 7120,6440
  Bottom Layer w20: C23.1@7122.01,6690 7210,6690
  Bottom Layer w25: U10.7@7008.07,6951.93 7040,6880 7175,6880 7210,6835 7210,6440 C17.1@7095,6440
  Bottom Layer w30: U10.7@7010,6960 C25.1@7010,7048.07
  other v1: 7175,6690
12V_ISO_3: C14.1 C20.1 C22.1 U7.11 U7.16 U9.7 | length 1283.9
  Top Layer w20: U7.11@7020,4805 U7.11@7032.99,4805 v1(7165,4805) ; U7.16@7025,4555 U7.16@7032.99,4555 v1(7170,4555)
  Bottom Layer w30: C22.1@7018.07,5180 U9.7@7020,5080 7020,5030 7059.3,4990.7 7179.3,4990.7 7210,4960 7210,4595 v1(7170,4555) 7165,4560 C14.1@7095,4560 C14.1@7100,4555 ; C20.1@7085,4805 C20.1@7095,4805 ; C20.1@7095,4815 7155,4815 v1(7165,4805) 7200,4805
GND: C2.2 C3.2 C4.2 C5.2 C6.2 C7.2 C9.2 C10.2 C12.2 C15.2 C16.2 C18.2 C19.2 C21.2 C24.2 C28.1 C29.1 C30.2 C32.2 C33.2 C34.2 C36.1 C37.2 C38.1 C41.1 C42.2 C43.1 C45.1 C46.2 C48.1 C51.1 C52.1 C53.2 C56.2 C58.2 C59.2 C61.2 C62.2 C63.1 C64.2 C67.1 C68.2 C69.1 C70.2 C71.2 C74.1 C75.1 C76.2 C77.1 C78.1 C79.2 C84.1 C85.2 C86.2 C88.1 C89.2 C91.2 C96.1 C97.1 C98.2 C100.2 C101.2 C103.1 C104.2 C105.1 C106.2 C107.2 C108.1 C109.2 C110.1 C111.2 D13.1 J4.2 J6.1 J6.2 J8.7 J8.10 J8.13 J8.16 J8.19 J8.22 J8.29 J8.35 J8.38 J8.46 J8.47 J8.65 J8.83 J8.97 J8.111 J10.135 J10.157 J10.179 R2.2 R10.2 R18.2 R22.1 R23.1 R31.1 R32.1 R39.1 R41.1 R60.1 R89.1 R90.1 R93.1 R105.1 R117.1 R122.1 R124.1 TP_GND1.1 TP_GND2.1 TP_GND3.1 U1.7 U2.8 U3.8 U4.8 U5.4 U5.5 U6.2 U7.4 U7.5 U8.4 U8.5 U9.2 U10.2 U11.5 U12.2 U13.2 U14.5 U15.2 U16.2 U17.5 U18.2 U19.9 U19.16 U20.2 U21.9 U21.16 U22.9 U22.10 U22.11 U23.2 U24.9 U24.16 U25.2 U26.5 U27.2 U28.2 U29.5 U30.2 U31.1 U32.2 | length 11265.1
  Top Layer w10: v1(6185,1155) 6204.92,1174.92 J8.7@6204.92,1278.94 ; J8.10@6236.42,1412.8 v1(6236.42,1526.42) ; v1(6299.41,1160.59) J8.13@6299.41,1278.94 ; v1(6310,1530) 6330.91,1509.09 J8.16@6330.91,1412.8 ; v1(6393.9,1166.1) J8.19@6393.9,1278.94 ; J8.22@6425.39,1412.8 6425.39,1501.39 v1(6450,1526) ; v1(6550,1165) 6551.38,1166.38 J8.29@6551.38,1278.94 ; v1(6645.87,1165.87) J8.35@6645.87,1278.94 ; J8.38@6677.36,1412.8 v1(6677.36,1527.36) ; v1(6780,1530) 6803.35,1506.65 J8.46@6803.35,1412.8 ; v1(6815,1155) 6834.84,1174.84 J8.47@6834.84,1278.94 ; v1(7244.29,1160.71) J8.65@7244.29,1278.94 ; v1(7527.76,1162.76) J8.83@7527.76,1278.94 ; v1(7725,1160) 7748.23,1183.23 J8.97@7748.23,1278.94 ; J8.111@7968.7,1278.94 7970,1130 v1(7980,1105) ; v1(9105,905) 9105,832.2 U31.1@9106.97,830.24 ; v1(9141.93,1166.93) J10.135@9141.93,1278.94 ; v1(9488.39,1168.39) J10.157@9488.39,1278.94 ; v1(9834.84,1164.84) J10.179@9834.84,1278.94
  Top Layer w15: v1(8880,1058) 8880,986.02 D13.1@8881.34,984.68
  Top Layer w20: v1@6986.54,2128.46 C103.1@7050,2128.46 ; U5.4@7385,8075 U5.4@7386,8074 ; U5.5@7387.01,8125 v1(7470,8125) ; U5.4@7394.99,8075 v1(7470,8075) ; R31.1@7400,4366.54 7411.54,4355 v1(7475,4355) ; U8.4@7402.01,6590 v1(7475,6590) ; U7.4@7407.01,4705 v1(7475,4705) ; U7.5@7407.01,4755 v1(7474.02,4755) ; U8.5@7407.01,6640 v1(7484.02,6640) ; v1@7485,6200 R41.1@7485,6271.54 ; v1@7500,7740 R22.1@7500,7806.54 ; v1(7614.91,318.7) C104.2@7685,318.7 ; C15.2@7615,4960 7625,4950 v1(7700,4950) ; C9.2@7615,8275 v1(7680,8275) ; v1(7625,4427.4) R32.1@7625,4503.94 ; C16.2@7635,4730 v1@7690,4730 ; v1(7635,6295) R39.1@7635,6371.54 ; C19.2@7645,6545 v1(7715,6545) ; C18.2@7650,6800 v1(7715,6800) ; C10.2@7650,8080 v1(7735,8080) ; R23.1@7653.46,7885 v1(7655,7815) ; v1(7685,220) C104.2@7685,318.7 ; v1(7755.09,318.7) C104.2@7685,318.7 ; v1(7948.3,318.7) C106.2@8010,318.7 ; v1(8010,215) C106.2@8010,318.7 ; v1(8071.7,318.7) C106.2@8010,318.7 ; v1(9650,1050) R122.1@9720,1050
  Top Layer w25: U4.8@3128.52,2327.18 3133.78,2321.93 C6.2@3280,2321.93 ; R18.2@3273.5,2390 3273.5,2328.43 C6.2@3280,2321.93 ; C7.2@3380,2295 3353.07,2321.93 C6.2@3280,2321.93 ; U3.8@3980.83,1787.18 4037.19,1787.18 4060,1810 R10.2@4116.54,1810 ; v1(4811,925) 4811,1014.46 C41.1@4811.54,1015 ; C51.1@4820,1434.76 4865.24,1480 v1(4905,1480) C52.1@4905,1422.8 ; v1(4904.57,389.88) U11.5@4904.57,440 ; v1(4904.57,715.43) U14.5@4904.57,765 ; U17.5@4909.57,1116.3 4953.7,1116.3 v1(4975,1095) ; v1(5010.77,1899.23) C75.1@5065.96,1899.23 5084.47,1917.74 R90.1@5144.47,1917.74 ; v1(5018,2082) 5075.2,2082 C74.1@5075.96,2081.24 5114.47,2042.74 R89.1@5149.47,2042.74 ; v1(5021.5,956.5) C42.2@5021.5,1010 ; C29.1@5077.8,705 v1(5140,705) ; C28.1@5079.76,625 v1(5145,625) ; U2.8@5081.54,2622.19 5152.8,2622.19 5174.98,2600 R2.2@5209.33,2600 ; v1(5174.8,1324.8) C61.2@5235,1324.8 5238.5,1321.3 C59.2@5308.5,1321.3 ; v1(5200,1025) 5252.5,1025 C48.1@5260,1017.5 5330,1017.5 C46.2@5333.5,1021 ; v1(5218.5,628.5) C37.2@5275,628.5 5278.5,625 C34.2@5343.5,625 ; C53.2@5250,233.46 v1(5318.46,233.46) ; U18.2@5420,1250.43 5420,1285 v1(5445,1310) ; v1(5423,167) 5433.5,167 5450.3,183.8 5470.69,183.8 5470.69,204.19 C36.1@5491.5,225 ; U15.2@5430,884.13 5430,910 5460,940 v1(5485,940) ; U12.2@5445,549.13 5445,580 v1(5470,605) ; C56.2@5587.5,1042 5611.5,1031.3 5645,1031.3 C58.2@5698.5,1031.3 ; U22.9@5600.96,1887.74 v1(5657.26,1887.74) ; U22.10@5600.96,1937.74 5681.74,1937.74 v1(5684,1940) ; U22.11@5600.96,1987.74 v1(5657.74,1987.74) ; C43.1@5611.5,710 5665,710 v1(5685,730) 5698.5,743.5 C45.1@5698.5,795 ; C30.2@5631.5,375 5695,375 5713.5,393.5 C33.2@5713.5,445 ; C32.2@5661.5,140 v1@5715,140 ; U13.2@5679.13,255 5705,255 5713.5,263.5 C38.1@5750,263.5 v1@5750,210 ; v1@5825,210 R60.1@5825,263.5 ; R93.1@5842.46,2057.74 5909.26,2057.74 C78.1@5935.29,2083.77 v1(5988.77,2083.77) ; C91.2@7761.93,3244.37 v1(7761.93,3308.07)
  Bottom Layer w10: U6.2@7490,8420 U6.2@7490,8425 ; U9.2@7515,5080 U9.2@7520,5080
  Bottom Layer w15: v1(8650,329) R124.1@8650,390
  Bottom Layer w20: U24.9@2770,4077.01 v1(2770,4150) ; U21.9@2820,5946.69 v1(2820,6020) ; C77.1@3020,4283.46 v1(3020,4345) ; C67.1@3070,6148.46 v1(3070,6210) ; U24.16@3120,4077.01 v1(3120,4145) ; C76.2@3120,4295 v1(3120,4355) ; U21.16@3170,5946.69 v1(3170,6015) ; C68.2@3175,6160 v1(3175,6220) ; C24.2@7480,7056.93 7480,6985 U10.2@7510,6960 ; C21.2@7484.37,5185 7484.37,5110.63 U9.2@7515,5080 ; C105.1@8423.46,285 8423.46,236.54 8460,200 U32.2@8460,140
  Bottom Layer w25: U19.9@2765,7832.01 v1(2765,7900) ; C63.1@3015,8033.46 v1(3015,8095) ; U19.16@3115,7832.01 v1(3115,7900) ; C62.2@3115,8045 v1(3115,8105) ; U3.8@3980.83,1787.18 4187.58,1787.18 4221.93,1752.83 C4.2@4221.93,1715 4221.93,1677.93 4170,1626 C5.2@4170,1620 ; U2.8@5081.54,2622.19 5240.61,2622.19 5294.72,2568.07 C2.2@5294.72,2540 5294.72,2494.72 5247.8,2447.8 C3.2@5247.8,2435 ; C69.1@5385.96,1936.24 v1(5443.13,1936.24) 5443.44,1936.56 C70.2@5493.68,1936.56 ; v1(8123.06,1978.82) 8150,1979 C96.1@8186,2015 ; v1(8231.55,1903.45) C98.2@8285,1903.45 ; v1(8285,1992) C97.1@8285,2050.45 ; U30.2@8454.13,1705.01 8454.95,1705.82 8495,1705.82 8525,1675.82 C101.2@8525,1668.45 R117.1@8605,1668.45 8600,1673.45 C100.2@8600,1765.45 ; U29.5@8454.41,2205.43 v1(8500.43,2205.43) ; C84.1@8593.09,2014.77 8594,2013.85 v1(8594,1949) ; C85.2@8678.09,2038.27 8679,2037.36 v1(8679,1977) ; C88.1@8705,1663.45 v1(8705,1720) R105.1@8705,1765.45 ; C89.2@8780,1765.45 8780,1735 v1(8794,1721) 8815,1700 U27.2@8850.86,1700 ; U26.5@8864.41,2205.43 v1(8904.57,2205.43) ; v1(8868.5,1526.5) C86.2@8868.5,1580.01
  Bottom Layer w30: C12.2@7458.07,8520 7458.07,8456.93 U6.2@7490,8425
  Bottom Layer w40: U23.2@2355,5145 2360,5140 C71.2@2491.54,5140 ; U20.2@2365,6825 2370,6820 C64.2@2511.54,6820 ; U25.2@2380,3315 2385,3310 C79.2@2513.07,3310
  other v1: 5724,140 5751,201 5825,202 5712,383 9065,405 9065,450 9060,905 5643,1031.3 8600,1724 6976,2128 7700,4730 7480,6190 7500,7730
IL1_FDBK: C75.2 J8.15 J8.20 R88.2 TP_IL2.1 | length 2317
  Top Layer w10: R88.2@5144.47,1832.74 5069.47,1832.74 C75.2@5065.96,1836.24 5065.96,1729.04 5100,1695 5925,1695 6185,1955 TP_IL2.1@6335,1955 6370,1920 6370,1590 6393.9,1566.1 J8.20@6393.9,1412.8 6393.9,1368.9 6365,1340 6345,1340 6330.91,1325.91 J8.15@6330.91,1278.94 J8.15@6331.41,1278.43
IL1_N: R2.1 R86.1 U22.6 | length 1365.5
  Top Layer w10: R2.1@5271.5,2600 v1(5335,2600) ; R86.1@5290.96,1894.23 5297.46,1887.74 U22.6@5386.4,1887.74 5427.26,1887.74 v1(5445,1870)
  Bottom Layer w10: v1(5335,2600) 5360,2600 5410,2550 5410,2310 5160,2060 5160,1915 5205,1870 v1(5445,1870)
IL1_P: R1.2 R90.2 U22.5 | length 1216.7
  Top Layer w10: v1(5207.46,1973) R90.2@5207.46,1917.74 5240,1917.74 5260,1937.74 U22.5@5386.4,1937.74 ; R1.2@5274.29,2705 v1(5330,2705)
  Bottom Layer w10: v1(5207.46,1973) 5207.46,2047.46 5455,2295 5455,2635 5385,2705 v1(5330,2705)
IL2_FDBK: C74.2 J8.21 J8.27 R87.2 TP_IL1.1 | length 3225.2
  Top Layer w10: R87.2@5149.47,2142.74 5147.97,2144.23 C74.2@5075.96,2144.23 4954.23,2144.23 4915,2105 4915,1740 5000,1655 5935,1655 6090,1810 TP_IL1.1@6220,1810 ; J8.21@6425.39,1278.94 6425.9,1278.43 6425.9,1169.1 v1(6490,1105) 6491,1105 6518,1132 6518,1277.06 J8.27@6519.88,1278.94
  Bottom Layer w10: TP_IL1.1@6220,1810 6338,1692 6338,1576.75 6440,1474.75 6440,1155 v1(6490,1105)
IL2_N: R10.1 R85.1 U22.2 | length 1773.1
  Top Layer w10: R10.1@4183.46,1810 4265,1810 4300,1845 4300,2005 4510,2215 5400.93,2215 5445,2170.93 5445,2110 5422.74,2087.74 U22.2@5386.4,2087.74 5292.46,2087.74 R85.1@5285.96,2081.24
IL2_P: R9.2 R89.2 U22.3 | length 1906.8
  Top Layer w10: R9.2@4181.5,1890 4245,1890 4270,1915 4270,2015 4495,2240 5404.21,2240 5476.28,2167.93 5476.28,2067.54 5446.48,2037.74 U22.3@5386.4,2037.74 5217.46,2037.74 R89.2@5212.46,2042.74
IL3_FDBK: C78.2 J8.25 R92.1 TP_IL3.1 | length 1695.9
  Top Layer w10: R92.1@5841.5,2157 5881,2157 5895,2143 5931.53,2143 C78.2@5935.29,2146.76 v1@5986.76,2146.76 ; v1(6485,1165) 6488.39,1168.39 J8.25@6488.39,1278.94
  Bottom Layer w10: v1(5995,2146) 6018.24,2169.24 6340,2170 6495,2015 TP_IL3.1@6495,1815 6495,1470 6485,1460 v1(6485,1165)
IL3_N: R18.1 R91.1 U22.13 | length 2565
  Top Layer w10: R18.1@3336.5,2390 3600,2390 3725,2265 5502.87,2265 5545,2222.87 5545,2095.33 5552.6,2087.74 U22.13@5600.96,2087.74 5699.47,2087.74 R91.1@5700.96,2086.24
IL3_P: R17.2 R93.2 U22.12 | length 3534
  Top Layer w10: R17.2@3336.5,2470 3590,2470 3775,2285 6030,2285 6055,2260 6055,2050 6010.27,2005.27 5804.73,2005.27 5779.47,2030.53 R93.2@5779.47,2057.74 5747.74,2057.74 5727.74,2037.74 U22.12@5600.96,2037.74
NetC2_1: C2.1 C3.1 L1.1 U2.7 | length 282.5
  Bottom Layer w50: U2.7@5081.54,2547.18 5084.35,2550 5150.87,2550 C2.1@5160.87,2540 5167.8,2533.07 L1.1@5167.8,2345
NetC4_1: C4.1 C5.1 L3.1 U3.7 | length 311.3
  Bottom Layer w50: U3.7@3980.83,1712.18 4085.26,1712.18 C4.1@4088.07,1715 4088.07,1621.93 C5.1@4090,1620 4090,1520 L3.1@4085,1515
NetC6_1: C6.1 C7.1 L6.1 U4.7 | length 406.3
  Top Layer w50: U4.7@3128.52,2252.18 3192.63,2188.07 C6.1@3280,2188.07 3353.07,2188.07 C7.1@3380,2215 3490,2215 L6.1@3495,2220
NetC26_1: C26.1 R48.1 R51.2 U12.4 | length 364.1
  Top Layer w20: R51.2@5326.5,445 5403.46,445 U12.4@5407.6,440.87 5407.6,477.28 5425.31,495 5495.87,495 5532.36,458.5 R48.1@5560,458.5 C26.1@5630,458.5
NetC26_2: C26.2 R48.2 R53.1 U12.1 | length 243.2
  Top Layer w20: U12.1@5482.4,549.13 5532.36,549.13 R48.2@5560,521.5 C26.2@5630,521.5 5631.5,520 R53.1@5713.5,520
NetC31_1: C31.1 R50.2 R51.1 | length 202.3
  Top Layer w20: R50.2@5076.5,445 5151.5,445 C31.1@5170,463.5 5245,463.5 R51.1@5263.5,445
NetC31_2: C31.2 R54.2 R55.1 | length 202.3
  Top Layer w20: R54.2@5076.5,545 5151.5,545 C31.2@5170,526.5 5245,526.5 R55.1@5263.5,545
NetC34_1: C34.1 R55.2 R57.2 U12.3 | length 229.1
  Top Layer w20: R55.2@5326.5,545 5330.63,549.13 U12.3@5407.6,549.13 5407.6,623.9 C34.1@5406.5,625 R57.2@5406.5,695
NetC35_2: C35.2 R56.1 U11.3 | length 171
  Top Layer w20: C35.2@4376.5,430 R56.1@4376.5,500 4415,500 4420,495 U11.3@4475.43,495
NetC38_2: C38.2 R58.1 R60.2 U13.3 | length 235
  Top Layer w20: U13.3@5679.13,292.4 5682.4,292.4 5716.5,326.5 C38.2@5750,326.5 R60.2@5825,326.5 R58.1@5900,326.5
NetC39_1: C39.1 R63.1 R66.2 U15.4 | length 362.2
  Top Layer w20: R66.2@5311.5,795 5350,795 5369.13,775.87 U15.4@5392.6,775.87 5392.6,812.6 5405,825 5523.5,825 C39.1@5545,803.5 R63.1@5615,803.5
NetC39_2: C39.2 R63.2 R68.1 U15.1 | length 239.9
  Top Layer w20: U15.1@5467.4,884.13 5527.36,884.13 C39.2@5545,866.5 R63.2@5615,866.5 5618.5,870 R68.1@5698.5,870
NetC44_1: C44.1 R65.2 R66.1 | length 178.2
  Top Layer w20: R65.2@5081.5,795 5095,808.5 C44.1@5165,808.5 5178.5,795 R66.1@5248.5,795
NetC44_2: C44.2 R69.2 R70.1 | length 167
  Top Layer w20: R69.2@5081.5,880 5156.5,880 C44.2@5165,871.5 ; C44.2@5168.5,875 R70.1@5248.5,875
NetC46_1: C46.1 R70.2 R72.2 U15.3 | length 223.4
  Top Layer w20: R70.2@5311.5,875 5320.63,884.13 U15.3@5392.6,884.13 5392.6,947.1 R72.2@5396.5,951 C46.1@5396.5,1021
NetC47_2: C47.2 R71.1 U14.3 | length 166
  Top Layer w20: C47.2@4381.5,740 R71.1@4381.5,810 4386.5,815 U14.3@4475.43,815
NetC49_1: C49.1 R75.1 R78.2 U18.4 | length 369.7
  Top Layer w25: R78.2@5296.5,1156.3 5310.63,1142.17 U18.4@5382.6,1142.17 5382.6,1167.6 5411.3,1196.3 5468.7,1196.3 5500.2,1164.8 C49.1@5535,1164.8 R75.1@5610,1164.8
NetC49_2: C49.2 R75.2 R80.1 U18.1 | length 347.8
  Top Layer w25: U18.1@5457.4,1250.43 5512.36,1250.43 C49.2@5535,1227.8 R75.2@5610,1227.8 5657.2,1227.8 5698.5,1186.5 R80.1@5698.5,1106.3
NetC57_1: C57.1 R77.2 R78.1 | length 154.1
  Top Layer w25: R77.2@5086.5,1156.3 5151.5,1156.3 C57.1@5160,1164.8 5168.5,1156.3 R78.1@5233.5,1156.3
NetC57_2: C57.2 R81.2 R82.1 | length 154.1
  Top Layer w25: R81.2@5086.5,1236.3 5151.5,1236.3 C57.2@5160,1227.8 5168.5,1236.3 R82.1@5233.5,1236.3
NetC59_1: C59.1 R82.2 R84.2 U18.3 | length 237.4
  Top Layer w25: R82.2@5296.5,1236.3 5368.46,1236.3 U18.3@5382.6,1250.43 5382.6,1310.2 C59.1@5371.5,1321.3 R84.2@5371.5,1391.3
NetC60_2: C60.2 R83.1 U17.3 | length 194
  Top Layer w20: C60.2@4376.5,1055 R83.1@4376.5,1130 4412.8,1166.3 U17.3@4480.43,1166.3
NetC62_1: C62.1 C63.2 L9.1 U19.14 | length 336.6
  Bottom Layer w20: U19.14@3015,7832.01 C63.2@3015,7966.54 3113.46,7966.54 C62.1@3115,7965 3118.46,7961.54 L9.1@3215,7961.54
